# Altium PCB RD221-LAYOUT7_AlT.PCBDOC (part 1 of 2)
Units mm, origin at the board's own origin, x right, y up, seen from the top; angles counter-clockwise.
Board outline 85 x 108 mm, 4 copper layers (TOP, Mid-Layer 1, Mid-Layer 2, BOTTOM), stack 0.711 mm thick; 92 components, 59 nets, 620 pads, 607 vias.
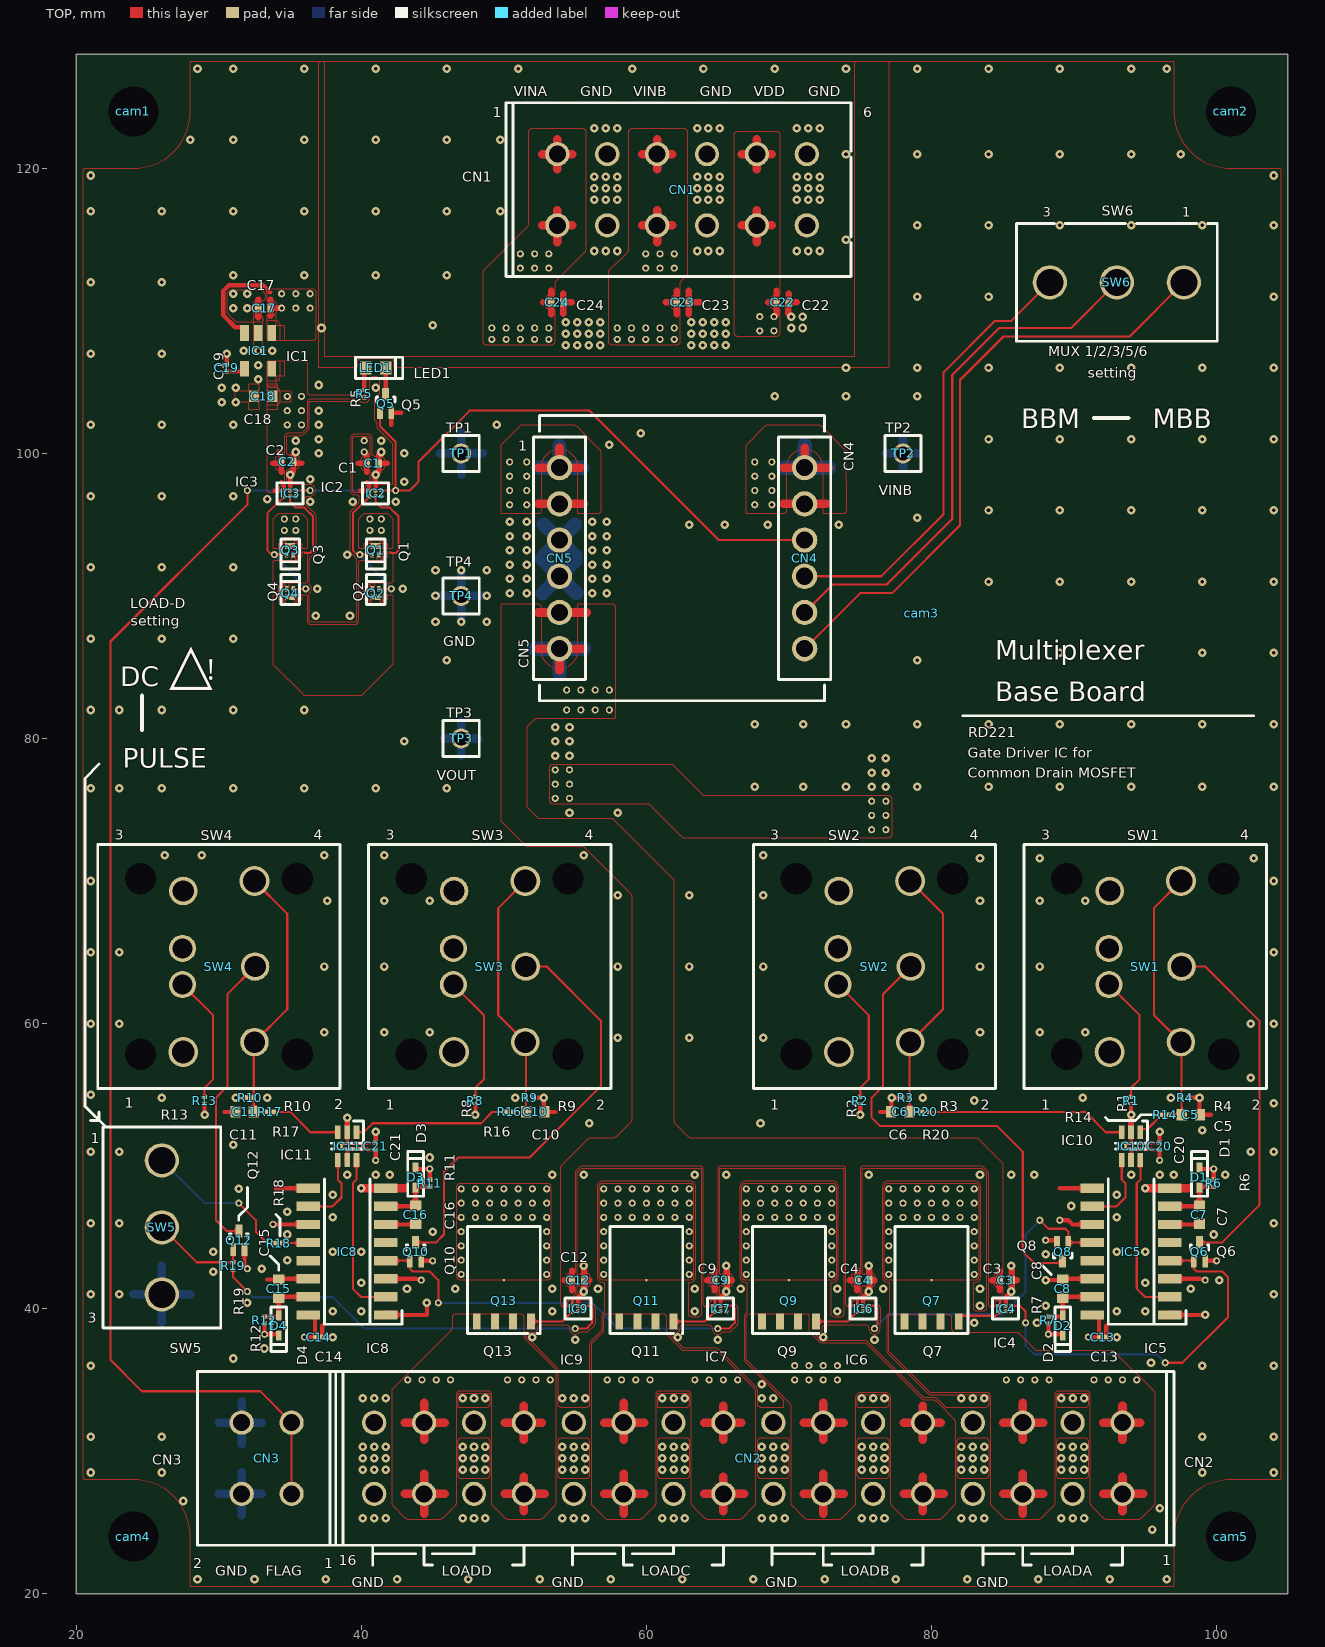
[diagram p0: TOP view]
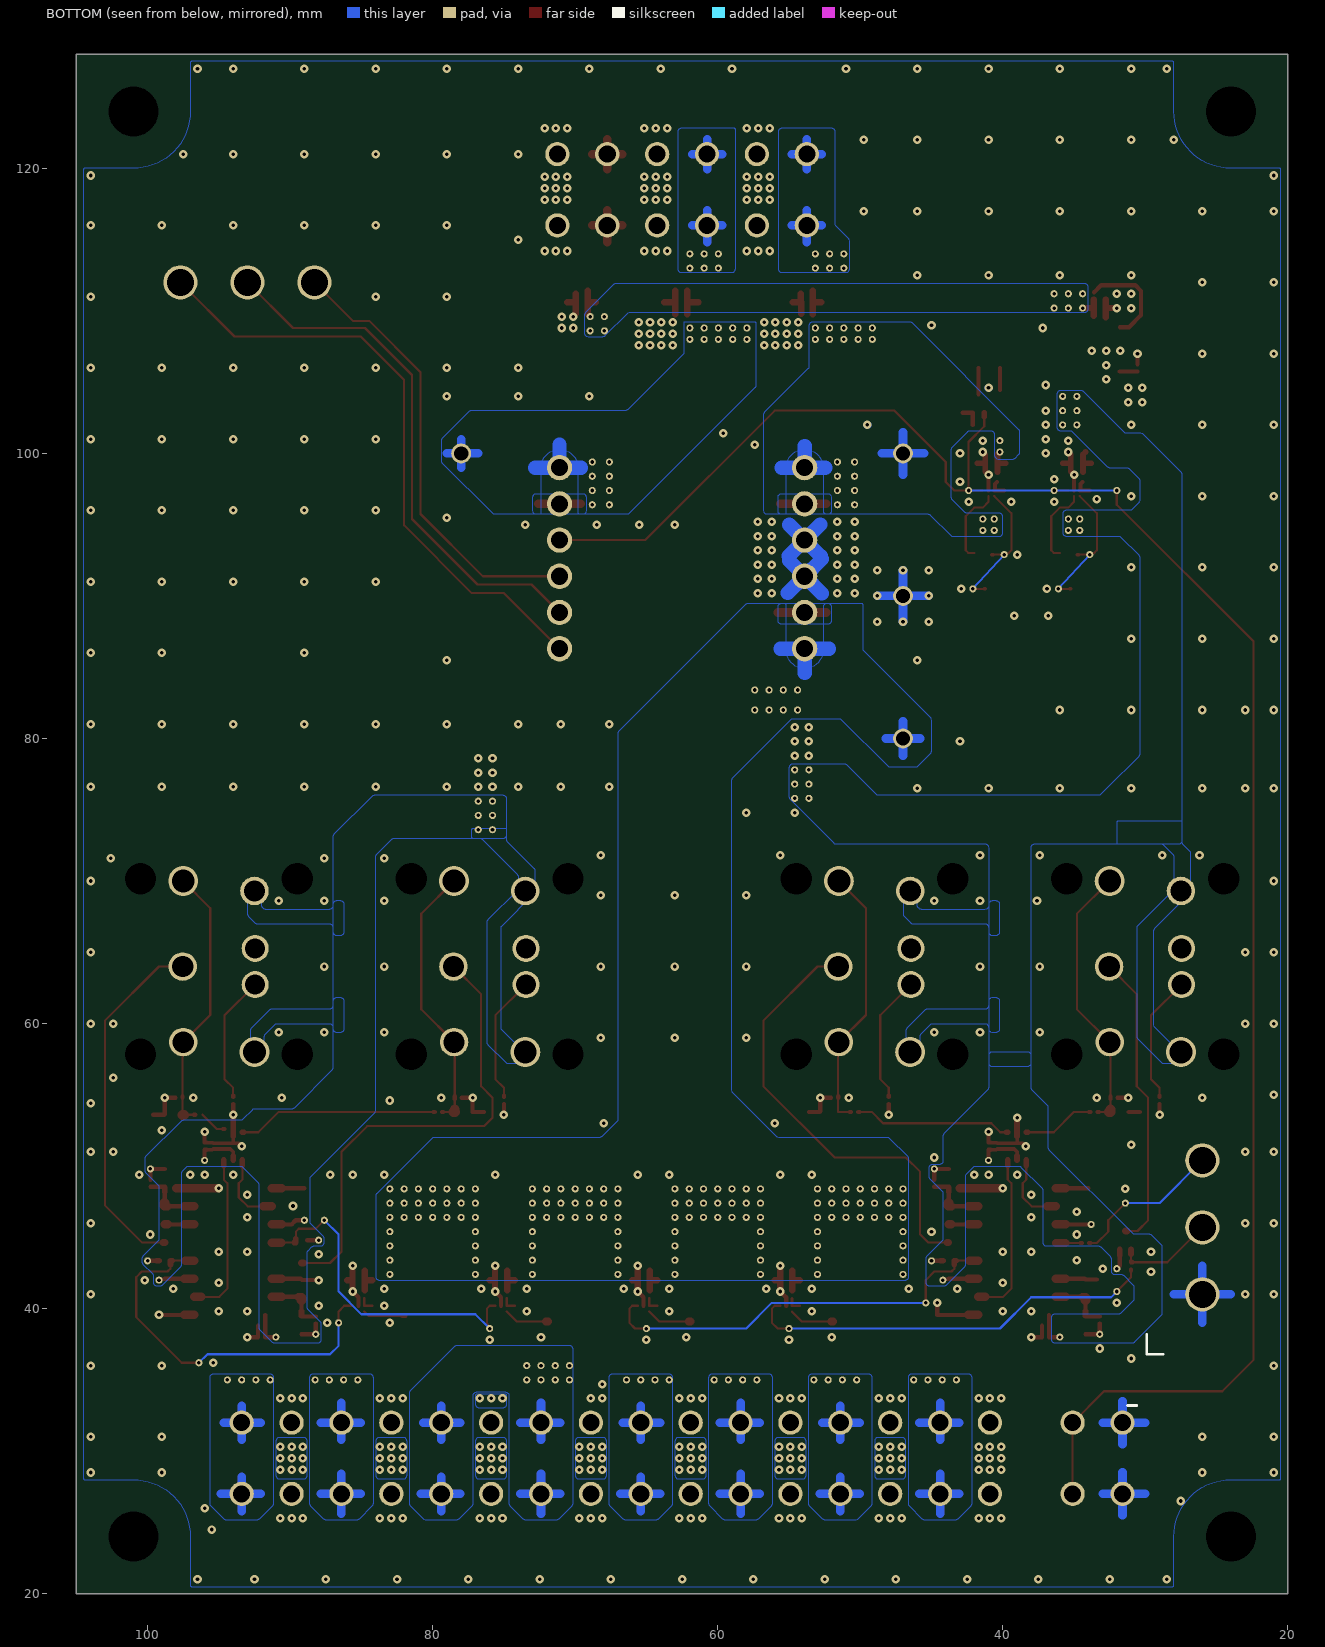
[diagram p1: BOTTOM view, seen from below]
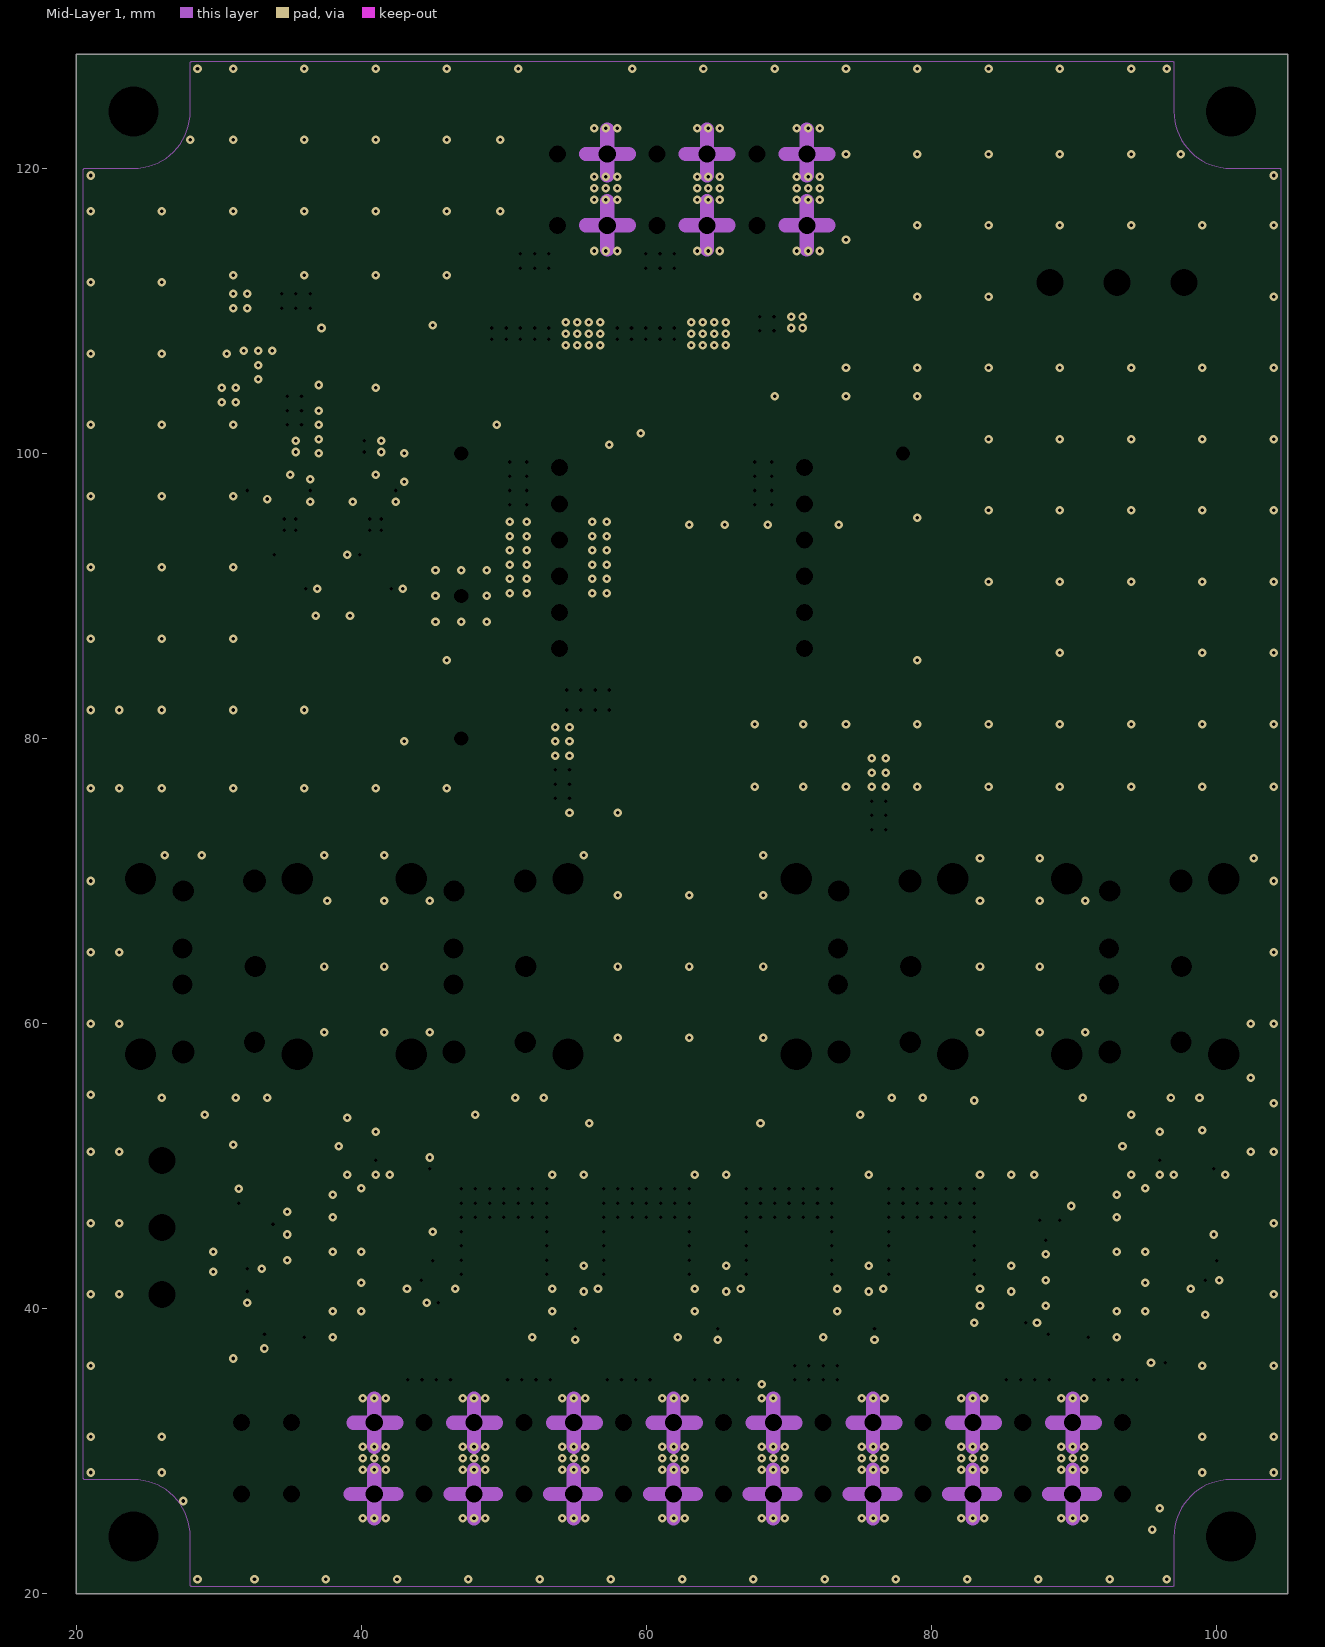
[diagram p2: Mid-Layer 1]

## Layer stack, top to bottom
Top Solder: solder mask 0.0102, Solder Resist, Dk 3.5
TOP: signal copper (thickness not stored)
Mid-Layer 1: signal copper 0.0356
Dielectric2: dielectric 0.32, FR-4, Dk 4.8
Mid-Layer 2: signal copper 0.0356
Dielectric3: dielectric 0.32, FR-4, Dk 4.8
BOTTOM: signal copper (thickness not stored)
Bottom Solder: solder mask 0.0102, Solder Resist, Dk 3.5

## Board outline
20,20 20,128 105,128 105,20

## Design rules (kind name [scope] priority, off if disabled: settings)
AssemblyTestPointUsage [All] p0: scope1count=1 scope1_0_kind=Board scope1_0_value=Board scope2count=1 scope2_0_kind=Board scope2_0_value=Board commentlength=0
AssemblyTestpoint [All] p0: scope1count=1 scope1_0_kind=Board scope1_0_value=Board scope2count=1 scope2_0_kind=Board scope2_0_value=Board commentlength=0
Clearance [All] p0: scope1count=1 scope1_0_kind=Board scope1_0_value=Board scope2count=1 scope2_0_kind=Board scope2_0_value=Board commentlength=0 gap=0.15
Clearance [All] p1: gap=0.15 ignorepadtopadclearanceinfootprint=TRUE except(0.5: Arc-Hole Track-Hole SMDPad-Hole THPad-Hole Via-Hole Fill-Hole Poly-Hole Region-Hole Text-Hole)
ComponentClearance [All] p0: scope1count=1 scope1_0_kind=Board scope1_0_value=Board scope2count=1 scope2_0_kind=Board scope2_0_value=Board commentlength=0 gap=0.254 collisioncheckmode=3
DiffPairsRouting [All] p0: scope1count=1 scope1_0_kind=Board scope1_0_value=Board scope2count=1 scope2_0_kind=Board scope2_0_value=Board commentlength=0
FabricationTestPointUsage [All] p0: scope1count=1 scope1_0_kind=Board scope1_0_value=Board scope2count=1 scope2_0_kind=Board scope2_0_value=Board commentlength=0 valid=0 allowmultiple=FALSE
FabricationTestpoint [All] p0: scope1count=1 scope1_0_kind=Board scope1_0_value=Board scope2count=1 scope2_0_kind=Board scope2_0_value=Board commentlength=0 side=3 testpointundercomponent=TRUE minsize=1.016 maxsize=2.54 preferedsize=1.524 minholesize=0 maxholesize=1.016 preferedholesize=0.813 testpointgrid=0.025
FanoutControl Fanout_BGA [All] p0 off: scope1count=1 scope1_0_kind=Board scope1_0_value=Board scope2count=1 scope2_0_kind=Board scope2_0_value=Board commentlength=69 // Protel DXP Scope 1 Expression Was: IsBGA   Fanout_BGA (Default Rule)
FanoutControl Fanout_LCC [All] p0 off: scope1count=1 scope1_0_kind=Board scope1_0_value=Board scope2count=1 scope2_0_kind=Board scope2_0_value=Board commentlength=69 // Protel DXP Scope 1 Expression Was: IsLCC   Fanout_LCC (Default Rule)
FanoutControl Fanout_SOIC [All] p0 off: scope1count=1 scope1_0_kind=Board scope1_0_value=Board scope2count=1 scope2_0_kind=Board scope2_0_value=Board commentlength=71 // Protel DXP Scope 1 Expression Was: IsSOIC   Fanout_SOIC (Default Rule)
FanoutControl Fanout_Small [All] p0 off: scope1count=1 scope1_0_kind=Board scope1_0_value=Board scope2count=1 scope2_0_kind=Board scope2_0_value=Board commentlength=84 // Protel DXP Scope 1 Expression Was: (CompPinCount < 5)   Fanout_Small (Default Rule)
FanoutControl Fanout_Default [All] p0: scope1count=1 scope1_0_kind=Board scope1_0_value=Board scope2count=1 scope2_0_kind=Board scope2_0_value=Board commentlength=30 // Fanout_Default (Default Rule)
Height [All] p0: scope1count=1 scope1_0_kind=Board scope1_0_value=Board scope2count=1 scope2_0_kind=Board scope2_0_value=Board commentlength=0
HoleSize [All] p0: scope1count=1 scope1_0_kind=Board scope1_0_value=Board scope2count=1 scope2_0_kind=Board scope2_0_value=Board commentlength=0 absolutevalues=TRUE maxlimit=100 minlimit=0.001 maxpercent=80.000 minpercent=20.000
HoleSize [All] p1: absolutevalues=TRUE maxlimit=100 minlimit=0.001 maxpercent=80.000 minpercent=20.000
HoleToHoleClearance [All] p0: scope1count=1 scope1_0_kind=Board scope1_0_value=Board scope2count=1 scope2_0_kind=Board scope2_0_value=Board commentlength=0
HoleToHoleClearance [All] p1: gap=0.4 allowstackedmicrovias=FALSE
LayerPairs [All] p0: scope1count=1 scope1_0_kind=Board scope1_0_value=Board scope2count=1 scope2_0_kind=Board scope2_0_value=Board commentlength=0 enforce=TRUE
MinimumSolderMaskSliver [All] p0: scope1count=1 scope1_0_kind=Board scope1_0_value=Board scope2count=1 scope2_0_kind=Board scope2_0_value=Board commentlength=0
MinimumSolderMaskSliver [All] p1: minsoldermaskwidth=0.1
NetAntennae [All] p0: scope1count=1 scope1_0_kind=Board scope1_0_value=Board scope2count=1 scope2_0_kind=Board scope2_0_value=Board commentlength=0
NetAntennae [All] p1: netantennaetolerance=100
PasteMaskExpansion [All] p0: scope1count=1 scope1_0_kind=Board scope1_0_value=Board scope2count=1 scope2_0_kind=Board scope2_0_value=Board commentlength=0 expansion=0
PlaneClearance [All] p0: scope1count=1 scope1_0_kind=Board scope1_0_value=Board scope2count=1 scope2_0_kind=Board scope2_0_value=Board commentlength=0 clearance=0.001
PlaneClearance [All] p1: clearance=0.001
PlaneConnect [All] p0: scope1count=1 scope1_0_kind=Board scope1_0_value=Board scope2count=1 scope2_0_kind=Board scope2_0_value=Board commentlength=0 planeconnectstyle=Direct reliefexpansion=0.508 reliefentries=4 reliefconductorwidth=0.254 reliefairgap=0.254
PlaneConnect [All] p1: planeconnectstyle=Direct reliefexpansion=0.508 reliefentries=4 reliefconductorwidth=0.254 reliefairgap=0.254
PolygonConnect [All] p0: scope1count=1 scope1_0_kind=Board scope1_0_value=Board scope2count=1 scope2_0_kind=Board scope2_0_value=Board commentlength=0 connectstyle=Direct reliefconductorwidth=0.254 reliefentries=4 polygonreliefangle="90 Angle"
PolygonConnect [All] p1: connectstyle=Direct reliefconductorwidth=0.254 reliefentries=4 polygonreliefangle="90 Angle" airgapwidth=0.254
RoutingCorners [All] p0: scope1count=1 scope1_0_kind=Board scope1_0_value=Board scope2count=1 scope2_0_kind=Board scope2_0_value=Board commentlength=0 cornerstyle=45-Degree minsetback=2.54 maxsetback=2.54
RoutingLayers [All] p0: scope1count=1 scope1_0_kind=Board scope1_0_value=Board scope2count=1 scope2_0_kind=Board scope2_0_value=Board commentlength=0 top layer=Automatic mid layer 1=Automatic mid layer 2=Automatic bottom layer=Automatic
RoutingPriority [All] p0: scope1count=1 scope1_0_kind=Board scope1_0_value=Board scope2count=1 scope2_0_kind=Board scope2_0_value=Board commentlength=0
RoutingTopology [All] p0: scope1count=1 scope1_0_kind=Board scope1_0_value=Board scope2count=1 scope2_0_kind=Board scope2_0_value=Board commentlength=0 topology=Shortest
RoutingVias [All] p0: scope1count=1 scope1_0_kind=Board scope1_0_value=Board scope2count=1 scope2_0_kind=Board scope2_0_value=Board commentlength=0 holewidth=0.1 width=0.1 viastyle="Through Hole" minholewidth=0.001 minwidth=0.001 maxholewidth=100 maxwidth=100
RoutingVias [All] p1: holewidth=0.1 width=0.1 viastyle="Through Hole" minholewidth=0.001 minwidth=0.001 maxholewidth=100 maxwidth=100
ShortCircuit [All] p0: scope1count=1 scope1_0_kind=Board scope1_0_value=Board scope2count=1 scope2_0_kind=Board scope2_0_value=Board commentlength=0 allowed=FALSE
SilkToBoardRegionClearance [All] p0: scope1count=1 scope1_0_kind=Board scope1_0_value=Board scope2count=1 scope2_0_kind=Board scope2_0_value=Board commentlength=0
SilkToSilkClearance [All] p0: scope1count=1 scope1_0_kind=Board scope1_0_value=Board scope2count=1 scope2_0_kind=Board scope2_0_value=Board commentlength=0
SilkToSilkClearance [All] p1: silktosilkclearance=0.001
SilkToSolderMaskClearance [All] p0 off: scope1count=1 scope1_0_kind=Board scope1_0_value=Board scope2count=1 scope2_0_kind=Board scope2_0_value=Board commentlength=44 // Protel DXP Scope 1 Expression Was: IsPad
SilkToSolderMaskClearance [IsPad] p1: minsilkscreentomaskgap=0 clearancetoexposedcopper=TRUE
SolderMaskExpansion [All] p0: scope1count=1 scope1_0_kind=Board scope1_0_value=Board scope2count=1 scope2_0_kind=Board scope2_0_value=Board commentlength=0 expansion=0.001
SolderMaskExpansion [All] p1: expansion=0.001
UnRoutedNet [All] p0: scope1count=1 scope1_0_kind=Board scope1_0_value=Board scope2count=1 scope2_0_kind=Board scope2_0_value=Board commentlength=0
UnpouredPolygon [All] p0: scope1count=1 scope1_0_kind=Board scope1_0_value=Board scope2count=1 scope2_0_kind=Board scope2_0_value=Board commentlength=0
Width [All] p0: scope1count=1 scope1_0_kind=Board scope1_0_value=Board scope2count=1 scope2_0_kind=Board scope2_0_value=Board commentlength=0 maxlimit=1000 minlimit=2539.975 preferedwidth=0
Width [All] p1: maxlimit=1000 minlimit=2539.975 preferedwidth=0 toplayer_minwidth=0 midlayer1_minwidth=0 midlayer2_minwidth=0 bottomlayer_minwidth=0 minimp=50.000000 maximp=50.000000 favimp=50.000000
22 further rules are at their usual default settings.

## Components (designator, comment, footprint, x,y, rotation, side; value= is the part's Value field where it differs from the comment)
C1 "KC00051KD" KC00051KD 40.8,99.3 r0 top
C2 "KC00051KD" KC00051KD 34.8,99.4 r0 top
C3 "KC00051KD" KC00051KD 85.2,42 r0 top
C4 "KC00051KD" KC00051KD 75.2,42 r0 top
C5 "KC00081KD" KC00081KD 98.2,53.6 r0 top
C6 "KC00081KD" KC00081KD 77.8,53.8 r180 top
C7 "KC00081KD" KC00081KD 98.8,46.6 r90 top
C8 "KC00081KD" KC00081KD 89.2,41.4 r270 top
C9 "KC00051KD" KC00051KD 65.2,42 r0 top
C10 "KC00081KD" KC00081KD 52.2,53.8 r0 top
C11 "KC00081KD" KC00081KD 31.8,53.8 r180 top
C12 "KC00051KD" KC00051KD 55.2,42 r0 top
C13 "KC00540KD" KC00540KD 92,38 r180 top
C14 "KC00540KD" KC00540KD 37,38 r180 top
C15 "KC00081KD" KC00081KD 34.2,41.4 r270 top
C16 "KC00081KD" KC00081KD 43.8,46.6 r270 top
C17 "KC00051KD" KC00051KD 33.2,110.2 r180 top
C18 "KC00081KD" KC00081KD 33.1,104 r180 top
C19 "KC00540KD" KC00540KD 30.55,106 r270 top
C20 "KC00540KD" KC00540KD 96,51.4 r270 top
C21 "KC00540KD" KC00540KD 41,51.4 r270 top
C22 "KC00051KD" KC00051KD 69.55,110.6 r0 top
C23 "KC00051KD" KC00051KD 62.55,110.6 r0 top
C24 "KC00051KD" KC00051KD 53.75,110.6 r0 top
cam1 "NTC350" NTC350 24,124 r180 top
cam2 "NTC350" NTC350 101,124 r180 top
cam3 "UTOS26N" UTOS26N 79.3,88.788 r0 top
cam4 "NTC350" NTC350 24,24 r180 top
cam5 "NTC350" NTC350 101,24 r180 top
CN1 "CU12010TD" CU12010TD 53.75,116 r0 top
CN2 "CU12030TD" CU12030TD 93.4,32 r180 top
CN3 "CU12020TD" CU12020TD 35.1,32 r180 top
CN4 "CU11170TD" CU11170TD 71.1,86.3 r90 top
CN5 "CU11170TD" CU11170TD 53.9,99 r270 top
D1 "D8101D1KD" D8101D1KD 98.8,49.2 r90 top
D2 "D8101D1KD" D8101D1KD 89.2,38.8 r270 top
D3 "D8101D1KD" D8101D1KD 43.8,49.2 r90 top
D4 "D8101D1KD" D8101D1KD 34.2,38.8 r270 top
IC1 "MM00631KD" MM00631KD 32.75,107.2 r180 top
IC2 "BA10620KD" BA10620KD 41,97.2 r0 top
IC3 "BA10620KD" BA10620KD 35,97.2 r0 top
IC4 "BA10620KD" BA10620KD 85.2,40 r0 top
IC5 "SP10580KD" SP10580KD 94,44 r90 top
IC6 "BA10620KD" BA10620KD 75.2,40 r0 top
IC7 "BA10620KD" BA10620KD 65.2,40 r0 top
IC8 "SP10580KD" SP10580KD 39,44 r90 top
IC9 "BA10620KD" BA10620KD 55.2,40 r0 top
IC10 "MM00451KD" MM00451KD 94,51.4 r180 top
IC11 "MM00451KD" MM00451KD 39,51.4 r180 top
LED1 "KC01110KD" KC01110KD 41,106 r0 top
Q1 "LA10710KD" LA10710KD 41,93.2 r90 top
Q2 "LA10710KD" LA10710KD 41,90.2 r270 top
Q3 "LA10710KD" LA10710KD 35,93.2 r90 top
Q4 "LA10710KD" LA10710KD 35,90.2 r270 top
Q5 "MM11010KD" MM11010KD 41.7,103.5 r0 top
Q6 "MM11010KD" MM11010KD 98.8,44 r0 top
Q7 "SN10261KD" SN10261KD 80,42 r0 top
Q8 "MM11010KD" MM11010KD 89.2,44 r180 top
Q9 "SN10261KD" SN10261KD 70,42 r0 top
Q10 "MM11010KD" MM11010KD 43.8,44 r0 top
Q11 "SN10261KD" SN10261KD 60,42 r0 top
Q12 "MM11010KD" MM11010KD 31.4,44.8 r0 top
Q13 "SN10261KD" SN10261KD 50,42 r0 top
R1 "KC00540KD" KC00540KD 94,54.6 r270 top
R2 "KC00540KD" KC00540KD 75,54.6 r270 top
R3 "KC00540KD" KC00540KD 78.2,54.8 r180 top
R4 "KC00540KD" KC00540KD 97.8,54.8 r0 top
R5 "KC00540KD" KC00540KD 40.2,104.2 r270 top
R6 "KC00540KD" KC00540KD 99.8,48.8 r270 top
R7 "KC00540KD" KC00540KD 88.2,39.2 r90 top
R8 "KC00540KD" KC00540KD 48,54.6 r270 top
R9 "KC00540KD" KC00540KD 51.8,54.8 r0 top
R10 "KC00540KD" KC00540KD 32.2,54.8 r180 top
R11 "KC00540KD" KC00540KD 44.8,48.8 r270 top
R12 "KC00540KD" KC00540KD 33.2,39.2 r90 top
R13 "KC00540KD" KC00540KD 29,54.6 r270 top
R14 "KC00540KD" KC00540KD 96.4,53.6 r0 top
R16 "KC00540KD" KC00540KD 50.4,53.8 r0 top
R17 "KC00540KD" KC00540KD 33.6,53.8 r0 top
R18 "KC00540KD" KC00540KD 34.2,44.6 r0 top
R19 "KC00540KD" KC00540KD 31,43 r270 top
R20 "KC00540KD" KC00540KD 79.6,53.8 r0 top
SW1 "OD11430TD" OD11430TD 95,64 r0 top
SW2 "OD11430TD" OD11430TD 76,64 r0 top
SW3 "OD11430TD" OD11430TD 49,64 r0 top
SW4 "OD11430TD" OD11430TD 30,64 r0 top
SW5 "OD11420TD" OD11420TD 26,50.4 r270 top
SW6 "OD11420TD" OD11420TD 97.7,112 r180 top
TP1 "DP002X0KD" DP002X0KD 47,100 r0 top
TP2 "DP002X0KD" DP002X0KD 78,100 r0 top
TP3 "DP002X0KD" DP002X0KD 47,80 r0 top
TP4 "DP002X0KD" DP002X0KD 47,90 r0 top

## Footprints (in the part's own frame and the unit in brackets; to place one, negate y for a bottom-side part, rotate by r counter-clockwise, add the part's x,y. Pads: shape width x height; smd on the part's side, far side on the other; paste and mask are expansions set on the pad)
BA10620KD [mm] "KC00080BKP"
  round 0.325 smd paste-0.325 mask+0: A1(-0.4,-0.2) A2(-0.4,0.2) B1(0,-0.2) B2(0,0.2) C1(0.4,-0.2) C2(0.4,0.2)
  silkscreen extent -0.91,-0.74 0.91,0.74
CU11170TD [mil] "KC00080BKP"
  round 70 / inner round 0 / far side round 70 hole 47.24 paste-70 mask+0: 1(0,0) 2(100,0) 3(200,0) 4(300,0) 5(400,0) 6(500,0)
  silkscreen extent -85,-72 585,72
CU12010TD [mm] "KC00080BKP"
  round 1.7 / inner round 0 / far side round 1.7 hole 1.2 paste-1.8 mask+0: 1(0,0) 1A(0,5) 2(3.5,0) 2A(3.5,5) 3(7,0) 3A(7,5) 4(10.5,0) 4A(10.5,5) 5(14,0) 5A(14,5) 6(17.5,0) 6A(17.5,5)
  silkscreen extent -3.6,-3.6 20.6,8.6
CU12020TD [mm] "KC00080BKP"
  round 1.7 / inner round 0 / far side round 1.7 hole 1.2 paste-1.8 mask+0: 1(0,0) 1A(0,5) 2(3.5,0) 2A(3.5,5)
  silkscreen extent -3.6,-3.6 6.6,8.6
CU12030TD [mm] "KC00080BKP"
  round 1.7 / inner round 0 / far side round 1.7 hole 1.2 paste-1.8 mask+0: 1(0,0) 1A(0,5) 2(3.5,0) 2A(3.5,5) 3(7,0) 3A(7,5) 4(10.5,0) 4A(10.5,5) 5(14,0) 5A(14,5) 6(17.5,0) 6A(17.5,5) 7(21,0) 7A(21,5) 8(24.5,0) 8A(24.5,5) 9(28,0) 9A(28,5) 10(31.5,0) 10A(31.5,5) 11(35,0) 11A(35,5) 12(38.5,0) 12A(38.5,5) 13(42,0) 13A(42,5) 14(45.5,0) 14A(45.5,5) 15(49,0) 15A(49,5) 16(52.5,0) 16A(52.5,5)
  silkscreen extent -3.6,-3.6 55.6,8.6
D8101D1KD [mm] "KC00080BKP"
  rect 0.7x0.4 smd paste-0.7 mask+0: A(-0.7,0) C(0.7,0)
  silkscreen extent -1.32,-0.55 1.82,0.55
DP002X0KD [mil] "KC00080BKP"
  round 55 / inner round 0 / far side round 55 hole 39.37 paste-55 mask+0: 1(0,0)
  silkscreen extent -50,-50 50,50
KC00051KD [mm] "KC00080BKP"
  rect 0.45x0.55 smd paste-0.55 mask+0: 1(-0.425,0) 2(0.425,0)
KC00081KD [mm] "KC00080BKP"
  rect 0.72x0.8 smd paste-0.8 mask+0: 1(-0.64,0) 2(0.64,0)
KC00540KD [mm] "KC00080BKP"
  rect 0.3x0.35 smd paste-0.35 mask+0: 1(-0.25,0) 2(0.25,0)
KC01110KD [mm] "KC00080BKP"
  rect 0.8x0.9 smd paste-0.9 mask+0: A(-0.7,0) C(0.7,0)
  silkscreen extent -1.4,-0.75 1.9,0.75
LA10710KD [mm] "KC00080BKP"
  rect 0.4x0.7 smd paste-0.7 mask+0: D(0.3,0)
  rect 0.4x0.25 smd paste-0.4 mask+0: G(-0.3,0.225) S(-0.3,-0.225)
  silkscreen extent -1.3,-0.65 0.8,0.65
MM00451KD [mm] "KC00080BKP"
  rect 0.4x0.95 smd paste-0.95 mask+0: 1(-0.65,-0.975) 2(0,-0.975) 3(0.65,-0.975) 4(0.65,0.975) 5(0,0.975) 6(-0.65,0.975)
  silkscreen extent -1.15,-1.75 1.1,0.2
MM00631KD [mm] "KC00080BKP"
  rect 0.6x1.1 smd paste-1.1 mask+0: 1(-0.95,-1.25) 2(0,-1.25) 3(0.95,-1.25) 4(0.95,1.25) 5(-0.95,1.25)
MM11010KD [mm] "KC00080BKP"
  rect 0.4x0.9 smd paste-0.9 mask+0: B(-0.4,-0.65) E(0.4,-0.65)
  rect 0.5x0.9 smd paste-0.9 mask+0: C(0,0.65)
  silkscreen extent -0.65,0.1 0.65,0.45
NTC350 [mm] "KC00080BKP"
  round 0 hole 3.5 unplated paste-4.064 mask+0: ""(0,0)
OD11420TD [mm] "KC00080BKP"
  round 2.4 / inner round 0 / far side round 2.4 hole 1.9 paste-2.5 mask+0: 1(0,0) 2(4.7,0) 3(9.4,0)
  silkscreen extent -2.35,-4.13 11.75,4.13
OD11430TD [mm] "KC00080BKP"
  round 2.1 / inner round 0 / far side round 2.1 hole 1.6 paste-2.2 mask+0: 1(-2.5,-6) 4(2.5,6)
  round 2 / inner round 0 / far side round 2 hole 1.5 paste-2.1 mask+0: 2(2.5,-5.3) 3(-2.5,5.3) LC(2.54,0)
  round 1.9 / inner round 0 / far side round 1.9 hole 1.4 paste-2 mask+0: L1(-2.55,1.27) L2(-2.55,-1.27)
  round 0 hole 2.2 unplated paste-2.54 mask+0: ""(-5.5,-6.15) ""(-5.5,6.15) ""(5.5,-6.15) ""(5.5,6.15)
  silkscreen extent -8.5,-8.55 8.5,8.55
SN10261KD [mm] "KC00080BKP"
  rect 0.55x1.1 smd paste-1.1 mask+0: 1(-1.905,-2.9) 2(-0.635,-2.9) 3(0.635,-2.9) 4(1.905,-2.9)
  round 0.178 smd paste-0.178 mask+0: 5(0,0)
  silkscreen extent -2.55,-3.75 2.55,3.75
SP10580KD [mm] "KC00080BKP"
  rect 0.65x1.65 smd paste-1.65 mask+0: 1(-4.445,-2.725) 2(-3.175,-2.725) 3(-1.905,-2.725) 4(-0.635,-2.725) 5(0.635,-2.725) 6(1.905,-2.725) 7(3.175,-2.725) 8(4.445,-2.725) 9(4.445,2.725) 10(3.175,2.725) 11(1.905,2.725) 12(0.635,2.725) 13(-0.635,2.725) 14(-1.905,2.725) 15(-3.175,2.725) 16(-4.445,2.725)
  silkscreen extent -5.1,-3.85 5.1,1.6
UTOS26N [mm] "KC00080BKP"

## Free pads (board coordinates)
  round 0.5 / inner round 0 / far side round 0.5 hole 0.25 paste-0.5 mask+0: ""(31.4,47.4) ""(32,41.2) ""(32,42.8) ""(32,97.4) ""(33.2,38.2) ""(33.8,45.905) ""(33.9,92.9) ""(34.4,110.2) ""(34.4,111.2) ""(34.6,94.6) ""(34.6,95.4) ""(34.8,102) ""(34.8,103) ""(34.8,104) ""(35.4,94.6) ""(35.4,95.4) ""(35.4,110.2) ""(35.4,111.2) ""(35.8,102) ""(35.8,103) ""(35.8,104) ""(36,38) ""(36.1,90.5) ""(36.4,97.4) ""(36.4,110.2) ""(36.4,111.2) ""(39.9,92.9) ""(40.2,100.1) ""(40.2,100.9) ""(40.6,94.6) ""(40.6,95.4) ""(41,50.4) ""(41.4,94.6) ""(41.4,95.4) ""(42.1,90.5) ""(42.4,97.4) ""(43.25,35) ""(44.2,42) ""(44.25,35) ""(44.8,49.8) ""(45,43.35) ""(45.25,35) ""(45.4,40.4) ""(46.25,35) ""(47,42.4) ""(47,43.4) ""(47,44.4) ""(47,45.4) ""(47,46.4) ""(47,47.4) ""(47,48.4) ""(48,46.4) ""(48,47.4) ""(48,48.4) ""(49,46.4) ""(49,47.4) ""(49,48.4) ""(49.15,108) ""(49.15,108.8) ""(50,46.4) ""(50,47.4) ""(50,48.4) ""(50.15,108) ""(50.15,108.8) ""(50.25,35) ""(50.4,96.4) ""(50.4,97.4) ""(50.4,98.4) ""(50.4,99.4) ""(51,46.4) ""(51,47.4) ""(51,48.4) ""(51.15,108) ""(51.15,108.8) ""(51.15,113) ""(51.15,114) ""(51.25,35) ""(51.6,96.4) ""(51.6,97.4) ""(51.6,98.4) ""(51.6,99.4) ""(52,46.4) ""(52,47.4) ""(52,48.4) ""(52.15,108) ""(52.15,108.8) ""(52.15,113) ""(52.15,114) ""(52.25,35) ""(53,42.4) ""(53,43.4) ""(53,44.4) ""(53,45.4) ""(53,46.4) ""(53,47.4) ""(53,48.4) ""(53.15,108) ""(53.15,108.8) ""(53.15,113) ""(53.15,114) ""(53.25,35) ""(53.6,75.8) ""(53.6,76.8) ""(53.6,77.8) ""(54.4,82) ""(54.4,83.4) ""(54.6,75.8) ""(54.6,76.8) ""(54.6,77.8) ""(55,38.6) ""(55.4,82) ""(55.4,83.4) ""(56.4,82) ""(56.4,83.4) ""(57,42.4) ""(57,43.4) ""(57,44.4) ""(57,45.4) ""(57,46.4) ""(57,47.4) ""(57,48.4) ""(57.25,35) ""(57.4,82) ""(57.4,83.4) ""(57.95,108) ""(57.95,108.8) ""(58,46.4) ""(58,47.4) ""(58,48.4) ""(58.25,35) ""(58.95,108) ""(58.95,108.8) ""(59,46.4) ""(59,47.4) ""(59,48.4) ""(59.25,35) ""(59.95,108) ""(59.95,108.8) ""(59.95,113) ""(59.95,114) ""(60,46.4) ""(60,47.4) ""(60,48.4) ""(60.25,35) ""(60.95,108) ""(60.95,108.8) ""(60.95,113) ""(60.95,114) ""(61,46.4) ""(61,47.4) ""(61,48.4) ""(61.95,108) ""(61.95,108.8) ""(61.95,113) ""(61.95,114) ""(62,46.4) ""(62,47.4) ""(62,48.4) ""(63,42.4) ""(63,43.4) ""(63,44.4) ""(63,45.4) ""(63,46.4) ""(63,47.4) ""(63,48.4) ""(63.4,35) ""(64.4,35) ""(65,38.6) ""(65.4,35) ""(66.4,35) ""(67,42.4) ""(67,43.4) ""(67,44.4) ""(67,45.4) ""(67,46.4) ""(67,47.4) ""(67,48.4) ""(67.6,96.4) ""(67.6,97.4) ""(67.6,98.4) ""(67.6,99.4) ""(67.95,108.6) ""(67.95,109.6) ""(68,46.4) ""(68,47.4) ""(68,48.4) ""(68.8,96.4) ""(68.8,97.4) ""(68.8,98.4) ""(68.8,99.4) ""(68.95,108.6) ""(68.95,109.6) ""(69,46.4) ""(69,47.4) ""(69,48.4) ""(70,46.4) ""(70,47.4) ""(70,48.4) ""(70.4,35) ""(70.4,36) ""(71,46.4) ""(71,47.4) ""(71,48.4) ""(71.4,35) ""(71.4,36) ""(72,46.4) ""(72,47.4) ""(72,48.4) ""(72.4,35) ""(72.4,36) ""(73,42.4) ""(73,43.4) ""(73,44.4) ""(73,45.4) ""(73,46.4) ""(73,47.4) ""(73,48.4) ""(73.4,35) ""(73.4,36) ""(75.8,73.6) ""(75.8,74.6) ""(75.8,75.6) ""(76,38.6) ""(76.8,73.6) ""(76.8,74.6) ""(76.8,75.6) ""(77,42.4) ""(77,43.4) ""(77,44.4) ""(77,45.4) ""(77,46.4) ""(77,47.4) ""(77,48.4) ""(78,46.4) ""(78,47.4) ""(78,48.4) ""(79,46.4) ""(79,47.4) ""(79,48.4) ""(80,46.4) ""(80,47.4) ""(80,48.4) ""(81,46.4) ""(81,47.4) ""(81,48.4) ""(82,46.4) ""(82,47.4) ""(82,48.4) ""(83,42.4) ""(83,43.4) ""(83,44.4) ""(83,45.4) ""(83,46.4) ""(83,47.4) ""(83,48.4) ""(85.25,35) ""(86.25,35) ""(86.6,39) ""(87.25,35) ""(87.6,46.2) ""(88,44.8) ""(88.2,38.2) ""(88.25,35) ""(89,46.2) ""(91,38) ""(91.4,35) ""(92.4,35) ""(93.4,35) ""(94.4,35) ""(96,50.4) ""(96.4,36.2) ""(99.2,42) ""(99.8,49.8) ""(100,43.35)

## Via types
v1: diameter 0.6, hole 0.25, TOP to BOTTOM, 607 vias

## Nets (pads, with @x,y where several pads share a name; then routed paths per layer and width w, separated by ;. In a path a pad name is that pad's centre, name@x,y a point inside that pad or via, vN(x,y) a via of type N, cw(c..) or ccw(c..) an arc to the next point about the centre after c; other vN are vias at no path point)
FLAG: CN3.1 CN3.1A CN4.4 IC2.C2 IC3.C2 pad.@32,97.4 pad.@36.4,97.4 pad.@42.4,97.4 Q5.B | length 138.4
  TOP w0.15: pad.@32,97.4 32,96.4 22.4,86.8 22.4,36.4 24.6,34.2 32.9,34.2 CN3.1@35.1,32 CN3.1A@35.1,27 ; IC3.C2@35.4,97.4 pad.@36.4,97.4 ; Q5.B@41.3,102.58 41.3,101.9 42.4,100.8 pad.@42.4,97.4 ; IC2.C2@41.4,97.4 pad.@42.4,97.4 ; CN4.4@71.1,93.92 65.08,93.92 56,103 47.6,103 44,99.4 44,98 43.4,97.4 pad.@42.4,97.4
  TOP w0.4: Q5.B@41.3,102.58 Q5.B@41.3,102.85
  BOTTOM w0.15: pad.@32,97.4 pad.@36.4,97.4 pad.@42.4,97.4
GND: C1.2 C2.2 C3.2 C4.2 C5.2 C6.2 C8.1 C9.2 C10.2 C11.2 C12.2 C13.1 C14.1 C15.1 C17.2 C18.2 C19.1 C20.1 C21.1 C22.2 C23.2 C24.2 CN1.2 CN1.2A CN1.4 CN1.4A CN1.6 CN1.6A CN2.2 CN2.2A CN2.4 CN2.4A CN2.6 CN2.6A CN2.8 CN2.8A CN2.10 CN2.10A CN2.12 CN2.12A CN2.14 CN2.14A CN2.16 CN2.16A CN3.2 CN3.2A CN5.3 CN5.4 IC1.2 IC2.B2 IC3.B2 IC4.B2 IC5.1 IC5.8 IC5.9 IC5.14 IC6.B2 IC7.B2 IC8.1 IC8.8 IC8.9 IC8.14 IC9.B2 IC10.2 IC11.2 Q5.E R1.2 R2.2 R3.2 R4.2 R8.2 R9.2 R10.2 R13.2 SW5.3 TP4.1 | length 259.1
  TOP w0.25: v1(38.4,51.4) 38.6,51.6 39,51.6 ; IC11.2@39,52.1 39,51.6 ; C21.1@40.868,51.65 40.45,51.65 40.4,51.6 39,51.6 ; v1(93.4,51.4) 93.6,51.6 94,51.6 ; IC10.2@94,52.1 94,51.6 ; C20.1@95.868,51.65 95.45,51.65 95.4,51.6 94,51.6
  TOP w0.3: v1(29,53.6) R13.2@29,54.35 ; 30.4,53.8 C11.2@31.16,53.8 ; C19.1@30.55,106.25 v1(30.55,107) ; v1(31.2,54.8) R10.2@31.95,54.8 ; 33.4,42.04 C15.1@34.2,42.04 ; 34,48.445 IC8.9@35.582,48.445 ; C15.1@34.255,42.095 IC8.14@35.582,42.095 ; IC3.B2@35,97.4 v1(35,98.5) ; 37.25,38.8 C14.1@37.25,38 v1(38,38) ; C21.1@40.868,51.65 C21.1@41,51.65 v1(41,52.4) ; IC2.B2@41,97.4 v1(41,98.5) ; 42.1,102 Q5.E@42.1,102.85 42.8,102.85 ; IC8.1@42.418,39.555 44.6,39.555 v1(44.6,40.4) ; v1(48,53.6) R8.2@48,54.35 ; R9.2@52.05,54.8 v1(52.8,54.8) C10.2@52.8,53.84 ; C10.2@52.84,53.8 53.6,53.8 ; IC9.B2@55.2,40.2 55.2,40.8 v1(55.6,41.2) ; IC7.B2@65.2,40.2 65.2,40.8 v1(65.6,41.2) ; v1(75,53.6) R2.2@75,54.35 ; IC6.B2@75.2,40.2 75.2,40.8 v1(75.6,41.2) ; 76.4,53.8 C6.2@77.16,53.8 ; C6.2@77.2,53.8 v1(77.2,54.8) R3.2@77.95,54.8 ; IC4.B2@85.2,40.2 85.2,40.8 v1(85.6,41.2) ; v1(88,42) C8.1@89.16,42 ; 89,48.445 IC5.9@90.582,48.445 ; C8.1@89.255,42.095 IC5.14@90.582,42.095 ; 92.25,38.8 C13.1@92.25,38 v1(93,38) ; v1(94,53.6) R1.2@94,54.35 ; C20.1@95.868,51.65 C20.1@96,51.65 v1(96,52.4) ; IC5.1@97.418,39.555 v1(99.2,39.555) ; R4.2@98.05,54.8 v1(98.8,54.8) C5.2@98.8,53.64 ; C5.2@98.84,53.6 99.6,53.6
  TOP w0.4: v1(35,98.5) 35.225,98.725 C2.2@35.225,99.3 ; v1(35.4,100.1) 35.225,99.925 C2.2@35.225,99.4 C2.2@35.225,99.3 ; 35.8,99.3 C2.2@35.225,99.3 ; IC11.2@39,52.1 IC11.2@39,52.375 v1(39,53.4) ; v1(41,98.5) 41.225,98.725 C1.2@41.225,99.3 ; v1(41.4,100.1) 41.225,99.925 C1.2@41.225,99.3 ; 41.8,99.3 C1.2@41.225,99.3 ; IC10.2@94,52.1 IC10.2@94,52.375 v1@94,53.4
  TOP w0.45: v1(32,110.2) C17.2@32.775,110.2 ; 32.775,109.55 C17.2@32.775,110.2 ; 32.775,110.8 C17.2@32.775,110.2 ; 54.15,109.8 C24.2@54.15,110.6 ; 54.175,111.2 C24.2@54.175,110.6 54.75,110.6 ; v1@55.625,41.4 C12.2@55.625,42 ; 55.625,42.65 C12.2@55.625,42 ; 56,42 C12.2@55.625,42 ; 62.975,109.775 C23.2@62.975,110.6 ; 62.975,111.4 C23.2@62.975,110.6 ; 63.75,110.6 C23.2@62.975,110.6 ; v1@65.625,41.4 C9.2@65.625,42 ; 65.625,42.65 C9.2@65.625,42 ; 66,42 C9.2@65.625,42 ; v1@69.95,109.8 C22.2@69.95,110.6 ; 69.975,111.2 C22.2@69.975,110.6 70.55,110.6 ; v1@75.625,41.4 C4.2@75.625,42 ; 75.625,42.65 C4.2@75.625,42 ; 76,42 C4.2@75.625,42 ; v1@85.625,41.4 C3.2@85.625,42 ; 85.625,42.65 C3.2@85.625,42 ; 86,42 C3.2@85.625,42
  TOP w0.6: IC8.14@35.582,42.095 IC8.14@36.275,42.095 ; IC8.9@35.582,48.445 IC8.9@36.275,48.445 ; v1(40,48.445) IC8.8@41.725,48.445 43,48.445 ; IC8.1@41.725,39.555 IC8.1@42.418,39.555 ; IC5.14@90.582,42.095 IC5.14@91.275,42.095 ; IC5.9@90.582,48.445 IC5.9@91.275,48.445 ; v1(95,48.445) IC5.8@96.725,48.445 98,48.445 ; IC5.1@96.725,39.555 IC5.1@97.418,39.555
  Mid-Layer 1 w1: 39.25,27 CN2.16A@40.9,27 ; 39.45,32 CN2.16@40.9,32 ; v1(40.9,25.3) CN2.16A@40.9,27 ; v1(40.9,28.7) CN2.16A@40.9,27 ; v1(40.9,30.3) CN2.16@40.9,32 ; v1(40.9,33.7) CN2.16@40.9,32 ; 42.45,27 CN2.16A@40.9,27 ; 42.45,32 CN2.16@40.9,32 ; 46.25,27 CN2.14A@47.9,27 ; 46.45,32 CN2.14@47.9,32 ; v1(47.9,25.3) CN2.14A@47.9,27 ; v1(47.9,28.7) CN2.14A@47.9,27 ; v1(47.9,30.3) CN2.14@47.9,32 ; v1(47.9,33.7) CN2.14@47.9,32 ; 49.45,27 CN2.14A@47.9,27 ; 49.45,32 CN2.14@47.9,32 ; 53.25,27 CN2.12A@54.9,27 ; 53.45,32 CN2.12@54.9,32 ; v1(54.9,25.3) CN2.12A@54.9,27 ; v1(54.9,28.7) CN2.12A@54.9,27 ; v1(54.9,30.3) CN2.12@54.9,32 ; v1(54.9,33.7) CN2.12@54.9,32 ; 55.75,116 CN1.2@57.25,116 ; 55.75,121 CN1.2A@57.25,121 ; 56.45,27 CN2.12A@54.9,27 ; 56.45,32 CN2.12@54.9,32 ; v1@57.25,114.3 CN1.2@57.25,116 ; v1@57.25,117.7 CN1.2@57.25,116 ; v1@57.25,119.5 CN1.2A@57.25,121 ; v1@57.25,122.7 CN1.2A@57.25,121 ; 58.75,116 CN1.2@57.25,116 ; 58.75,121 CN1.2A@57.25,121 ; 60.25,27 CN2.10A@61.9,27 ; 60.45,32 CN2.10@61.9,32 ; v1(61.9,25.3) CN2.10A@61.9,27 ; v1(61.9,28.7) CN2.10A@61.9,27 ; v1(61.9,30.3) CN2.10@61.9,32 ; v1(61.9,33.7) CN2.10@61.9,32 ; 62.75,116 CN1.4@64.25,116 ; 62.75,121 CN1.4A@64.25,121 ; 63.45,27 CN2.10A@61.9,27 ; 63.45,32 CN2.10@61.9,32 ; v1@64.25,114.3 CN1.4@64.25,116 ; v1@64.25,117.7 CN1.4@64.25,116 ; v1@64.25,119.5 CN1.4A@64.25,121 ; v1@64.25,122.7 CN1.4A@64.25,121 ; 65.75,116 CN1.4@64.25,116 ; 65.75,121 CN1.4A@64.25,121 ; 67.25,27 CN2.8A@68.9,27 ; 67.45,32 CN2.8@68.9,32 ; v1(68.9,25.3) CN2.8A@68.9,27 ; v1(68.9,28.7) CN2.8A@68.9,27 ; v1(68.9,30.3) CN2.8@68.9,32 ; v1(68.9,33.7) CN2.8@68.9,32 ; 69.75,116 CN1.6@71.25,116 ; 69.75,121 CN1.6A@71.25,121 ; 70.45,27 CN2.8A@68.9,27 ; 70.45,32 CN2.8@68.9,32 ; v1@71.25,114.3 CN1.6@71.25,116 ; v1@71.25,117.7 CN1.6@71.25,116 ; v1@71.25,119.5 CN1.6A@71.25,121 ; v1@71.25,122.7 CN1.6A@71.25,121 ; 72.75,116 CN1.6@71.25,116 ; 72.75,121 CN1.6A@71.25,121 ; 74.25,27 CN2.6A@75.9,27 ; 74.45,32 CN2.6@75.9,32 ; v1(75.9,25.3) CN2.6A@75.9,27 ; v1(75.9,28.7) CN2.6A@75.9,27 ; v1(75.9,30.3) CN2.6@75.9,32 ; v1(75.9,33.7) CN2.6@75.9,32 ; 77.45,27 CN2.6A@75.9,27 ; 77.45,32 CN2.6@75.9,32 ; 81.25,27 CN2.4A@82.9,27 ; 81.45,32 CN2.4@82.9,32 ; v1(82.9,25.3) CN2.4A@82.9,27 ; v1(82.9,28.7) CN2.4A@82.9,27 ; v1(82.9,30.3) CN2.4@82.9,32 ; v1(82.9,33.7) CN2.4@82.9,32 ; 84.45,27 CN2.4A@82.9,27 ; 84.45,32 CN2.4@82.9,32 ; 88.25,27 CN2.2A@89.9,27 ; 88.45,32 CN2.2@89.9,32 ; v1(89.9,25.3) CN2.2A@89.9,27 ; v1(89.9,28.7) CN2.2A@89.9,27 ; v1(89.9,30.3) CN2.2@89.9,32 ; v1(89.9,33.7) CN2.2@89.9,32 ; 91.45,27 CN2.2A@89.9,27 ; 91.45,32 CN2.2@89.9,32
  BOTTOM w0.6: 24,41 SW5.3@26,41 ; 26,39 SW5.3@26,41 ; 26,43 SW5.3@26,41 ; 28,41 SW5.3@26,41 ; 30,27 CN3.2A@31.6,27 ; 30,32 CN3.2@31.6,32 ; 31.6,25.5 CN3.2A@31.6,27 ; 31.6,28.5 CN3.2A@31.6,27 ; 31.6,30.5 CN3.2@31.6,32 ; 31.6,33.5 CN3.2@31.6,32 ; 33,27 CN3.2A@31.6,27 ; 33,32 CN3.2@31.6,32 ; v1(45.2,90) TP4.1@47,90 ; v1(47,88.2) TP4.1@47,90 ; v1(47,91.8) TP4.1@47,90 ; v1(48.8,90) TP4.1@47,90
  BOTTOM w1: 52.68,92.6 CN5.4@53.9,91.38 ; 52.7,90.18 CN5.4@53.9,91.38 ; 52.78,92.8 CN5.3@53.9,93.92 ; 52.8,95.02 CN5.3@53.9,93.92 ; 54.98,95 CN5.3@53.9,93.92 ; 55,92.48 CN5.4@53.9,91.38 ; 55.02,92.8 CN5.3@53.9,93.92 ; 55.08,90.2 CN5.4@53.9,91.38
  other v1: 28.5,21 32.5,21 37.5,21 42.5,21 47.5,21 52.5,21 57.5,21 62.5,21 67.5,21 72.5,21 77.5,21 82.5,21 87.5,21 92.5,21 96.5,21 95.5,24.5 40.1,25.3 41.7,25.3 47.1,25.3 48.7,25.3 54.1,25.3 55.7,25.3 61.1,25.3 62.7,25.3 68.1,25.3 69.7,25.3 75.1,25.3 76.7,25.3 82.1,25.3 83.7,25.3 89.1,25.3 90.7,25.3 96,26 27.5,26.5 21,28.5 26,28.5 99,28.5 104,28.5 40.1,28.7 41.7,28.7 47.1,28.7 48.7,28.7 54.1,28.7 55.7,28.7 61.1,28.7 62.7,28.7 68.1,28.7 69.7,28.7 75.1,28.7 76.7,28.7 82.1,28.7 83.7,28.7 89.1,28.7 90.7,28.7 40.1,29.5 40.9,29.5 41.7,29.5 47.1,29.5 47.9,29.5 48.7,29.5 54.1,29.5 54.9,29.5 55.7,29.5 61.1,29.5 61.9,29.5 62.7,29.5 68.1,29.5 68.9,29.5 69.7,29.5 75.1,29.5 75.9,29.5 76.7,29.5 82.1,29.5 82.9,29.5 83.7,29.5 89.1,29.5 89.9,29.5 90.7,29.5 40.1,30.3 41.7,30.3 47.1,30.3 48.7,30.3 54.1,30.3 55.7,30.3 61.1,30.3 62.7,30.3 68.1,30.3 69.7,30.3 75.1,30.3 76.7,30.3 82.1,30.3 83.7,30.3 89.1,30.3 90.7,30.3 21,31 26,31 99,31 104,31 40.1,33.7 41.7,33.7 47.1,33.7 48.7,33.7 54.1,33.7 55.7,33.7 61.1,33.7 62.7,33.7 68.1,33.7 75.1,33.7 76.7,33.7 82.1,33.7 83.7,33.7 89.1,33.7 90.7,33.7 68.1,34.7 21,36 99,36 104,36 95.4,36.2 31,36.5 33.2,37.2 55,37.8 65,37.8 76,37.8 52,38 62.2,38 72.4,38 83,39 87.4,39 38,39.8 40,39.8 53.4,39.8 63.4,39.8 73.4,39.8 93,39.8 95,39.8 83.4,40.2 88,40.2 32,40.4 21,41 23,41 104,41 43.2,41.4 46.6,41.4 53.4,41.4 56.6,41.4 63.4,41.4 66.6,41.4 73.4,41.4 76.6,41.4 83.4,41.4 98.2,41.4 40,41.8 95,41.8 100.2,42 29.6,42.6 33,42.8 55.6,43 65.6,43 75.6,43 85.6,43 34.8,43.4 88,43.8 29.6,44 38,44 40,44 93,44 95,44 34.8,45.2 99.8,45.2 45,45.4 21,46 23,46 104,46 38,46.4 93,46.4 34.8,46.8 89.8,47.2 38,48 93,48 31.4,48.4 39,49.4 41,49.4 42,49.4 53.4,49.4 55.6,49.4 63.4,49.4 65.6,49.4 75.6,49.4 83.4,49.4 85.6,49.4 87.2,49.4 94,49.4 96,49.4 97,49.4 100.6,49.4 44.8,50.6 21,51 23,51 102.4,51 104,51 31,51.5 99,52.5 56,53 68,53 104,54.4 83,54.6 26,54.8 33.4,54.8 50.8,54.8 79.4,54.8 90.6,54.8 96.8,54.8 21,55 102.4,56.2 58,59 63,59 68.2,59 37.4,59.4 41.6,59.4 44.8,59.4 83.4,59.4 87.6,59.4 90.8,59.4 21,60 23,60 102.4,60 104,60 37.4,64 41.6,64 58,64 63,64 68.2,64 83.4,64 87.6,64 21,65 23,65 104,65 37.6,68.6 41.6,68.6 44.8,68.6 83.4,68.6 87.6,68.6 90.8,68.6 58,69 63,69 68.2,69 21,70 104,70 83.4,71.6 87.6,71.6 102.6,71.6 26.2,71.8 28.8,71.8 37.4,71.8 41.6,71.8 55.6,71.8 68.2,71.8 54.6,74.8 58,74.8 21,76.5 23,76.5 26,76.5 31,76.5 36,76.5 41,76.5 46,76.5 67.6,76.6 71,76.6 74,76.6 75.8,76.6 76.8,76.6 79,76.6 84,76.6 89,76.6 94,76.6 99,76.6 104,76.6 75.8,77.6 76.8,77.6 75.8,78.6 76.8,78.6 53.6,78.8 54.6,78.8 43,79.8 53.6,79.8 54.6,79.8 53.6,80.8 54.6,80.8 67.6,81 71,81 74,81 79,81 84,81 89,81 94,81 99,81 104,81 21,82 23,82 26,82 31,82 36,82 46,85.5 79,85.5 89,86 99,86 104,86 21,87 26,87 31,87 45.2,88.2 48.8,88.2 36.8,88.6 39.2,88.6 50.4,90.2 51.6,90.2 56.2,90.2 57.2,90.2 36.9,90.5 42.9,90.5 84,91 89,91 94,91 99,91 104,91 50.4,91.2 51.6,91.2 56.2,91.2 57.2,91.2 45.2,91.8 48.8,91.8 21,92 26,92 31,92 50.4,92.2 51.6,92.2 56.2,92.2 57.2,92.2 39,92.9 50.4,93.2 51.6,93.2 56.2,93.2 57.2,93.2 50.4,94.2 51.6,94.2 56.2,94.2 57.2,94.2 63,95 65.5,95 68.5,95 73.5,95 50.4,95.2 51.6,95.2 56.2,95.2 57.2,95.2 79,95.5 84,96 89,96 94,96 99,96 104,96 36.4,96.6 39.4,96.6 42.4,96.6 33.4,96.8 21,97 26,97 31,97 43,98 36.4,98.2 37,100 43,100 57.4,100.6 35.4,100.9 41.4,100.9 37,101 84,101 89,101 94,101 99,101 104,101 59.6,101.4 21,102 26,102 31,102 37,102 49.5,102 37,103 30.2,103.6 31.2,103.6 69,104 74,104 79,104 30.2,104.6 31.2,104.6 41,104.6 37,104.8 32.75,105.2 74,106 79,106 84,106 89,106 94,106 99,106 104,106 32.75,106.2 21,107 26,107 31.75,107.2 32.75,107.2 33.75,107.2 54.35,107.6 55.15,107.6 55.95,107.6 56.75,107.6 63.15,107.6 63.95,107.6 64.75,107.6 65.55,107.6 54.35,108.4 55.15,108.4 55.95,108.4 56.75,108.4 63.15,108.4 63.95,108.4 64.75,108.4 65.55,108.4 37.2,108.8 70.15,108.8 70.95,108.8 45,109 54.35,109.2 55.15,109.2 55.95,109.2 56.75,109.2 63.15,109.2 63.95,109.2 64.75,109.2 65.55,109.2 70.15,109.6 70.95,109.6 31,110.2 79,111 84,111 104,111 31,111.2 32,111.2 21,112 26,112 31,112.5 36,112.5 41,112.5 46,112.5 56.35,114.2 57.15,114.2 57.95,114.2 63.55,114.2 64.35,114.2 65.15,114.2 70.55,114.2 71.35,114.2 72.15,114.2 74,115 79,116 84,116 89,116 94,116 99,116 104,116 21,117 26,117 31,117 36,117 41,117 46,117 49.75,117 56.35,117.8 57.15,117.8 57.95,117.8 63.55,117.8 64.35,117.8 65.15,117.8 70.55,117.8 71.35,117.8 72.15,117.8 56.35,118.6 57.15,118.6 57.95,118.6 63.55,118.6 64.35,118.6 65.15,118.6 70.55,118.6 71.35,118.6 72.15,118.6 56.35,119.4 57.15,119.4 57.95,119.4 63.55,119.4 64.35,119.4 65.15,119.4 70.55,119.4 71.35,119.4 72.15,119.4 21,119.5 104,119.5 74,121 79,121 84,121 89,121 94,121 97.5,121 28,122 31,122 36,122 41,122 46,122 49.75,122 56.35,122.8 57.15,122.8 57.95,122.8 63.55,122.8 64.35,122.8 65.15,122.8 70.55,122.8 71.35,122.8 72.15,122.8 28.5,127 31,127 36,127 41,127 46,127 51,127 59,127 64,127 69,127 74,127 79,127 84,127 89,127 94,127 96.5,127
LOADA: CN2.1 CN2.1A CN2.3 CN2.3A pad.@85.25,35 pad.@86.25,35 pad.@87.25,35 pad.@88.25,35 pad.@91.4,35 pad.@92.4,35 pad.@93.4,35 pad.@94.4,35 Q7.1 Q7.2 Q7.3 | length 42.4
  TOP w0.6: 85.05,27 CN2.3A@86.4,27 ; 85.05,32 CN2.3@86.4,32 ; 86.4,25.6 CN2.3A@86.4,27 ; 86.4,28.4 CN2.3A@86.4,27 ; 86.4,30.8 CN2.3@86.4,32 ; 86.4,33.4 CN2.3@86.4,32 ; 87.85,27 CN2.3A@86.4,27 ; 87.85,32 CN2.3@86.4,32 ; 92.05,27 CN2.1A@93.4,27 ; 92.05,32 CN2.1@93.4,32 ; 93.4,25.8 CN2.1A@93.4,27 ; 93.4,28.2 CN2.1A@93.4,27 ; 93.4,30.8 CN2.1@93.4,32 ; 93.4,33.2 CN2.1@93.4,32 ; 94.65,32 CN2.1@93.4,32 ; 94.85,27 CN2.1A@93.4,27
  BOTTOM w0.6: 85.05,27 CN2.3A@86.4,27 ; 85.05,32 CN2.3@86.4,32 ; 86.4,25.6 CN2.3A@86.4,27 ; 86.4,28.4 CN2.3A@86.4,27 ; 86.4,30.8 CN2.3@86.4,32 ; 86.4,33.4 CN2.3@86.4,32 ; 87.85,27 CN2.3A@86.4,27 ; 87.85,32 CN2.3@86.4,32 ; 92.05,27 CN2.1A@93.4,27 ; 92.05,32 CN2.1@93.4,32 ; 93.4,25.8 CN2.1A@93.4,27 ; 93.4,28.2 CN2.1A@93.4,27 ; 93.4,30.8 CN2.1@93.4,32 ; 93.4,33.2 CN2.1@93.4,32 ; 94.65,32 CN2.1@93.4,32 ; 94.85,27 CN2.1A@93.4,27
LOADB: CN2.5 CN2.5A CN2.7 CN2.7A pad.@70.4,35 pad.@70.4,36 pad.@71.4,35 pad.@71.4,36 pad.@72.4,35 pad.@72.4,36 pad.@73.4,35 pad.@73.4,36 Q9.1 Q9.2 Q9.3 | length 42.4
  TOP w0.6: 71.05,27 CN2.7A@72.4,27 ; 71.05,32 CN2.7@72.4,32 ; 72.4,25.6 CN2.7A@72.4,27 ; 72.4,28.4 CN2.7A@72.4,27 ; 72.4,30.8 CN2.7@72.4,32 ; 72.4,33.4 CN2.7@72.4,32 ; 73.85,27 CN2.7A@72.4,27 ; 73.85,32 CN2.7@72.4,32 ; 78.05,27 CN2.5A@79.4,27 ; 78.05,32 CN2.5@79.4,32 ; 79.4,25.8 CN2.5A@79.4,27 ; 79.4,28.2 CN2.5A@79.4,27 ; 79.4,30.8 CN2.5@79.4,32 ; 79.4,33.2 CN2.5@79.4,32 ; 80.65,32 CN2.5@79.4,32 ; 80.85,27 CN2.5A@79.4,27
  BOTTOM w0.6: 71.05,27 CN2.7A@72.4,27 ; 71.05,32 CN2.7@72.4,32 ; 72.4,25.6 CN2.7A@72.4,27 ; 72.4,28.4 CN2.7A@72.4,27 ; 72.4,30.8 CN2.7@72.4,32 ; 72.4,33.4 CN2.7@72.4,32 ; 73.85,27 CN2.7A@72.4,27 ; 73.85,32 CN2.7@72.4,32 ; 78.05,27 CN2.5A@79.4,27 ; 78.05,32 CN2.5@79.4,32 ; 79.4,25.8 CN2.5A@79.4,27 ; 79.4,28.2 CN2.5A@79.4,27 ; 79.4,30.8 CN2.5@79.4,32 ; 79.4,33.2 CN2.5@79.4,32 ; 80.65,32 CN2.5@79.4,32 ; 80.85,27 CN2.5A@79.4,27
LOADC: CN2.9 CN2.9A CN2.11 CN2.11A pad.@57.25,35 pad.@58.25,35 pad.@59.25,35 pad.@60.25,35 pad.@63.4,35 pad.@64.4,35 pad.@65.4,35 pad.@66.4,35 Q11.1 Q11.2 Q11.3 | length 42.4
  TOP w0.6: 57.05,27 CN2.11A@58.4,27 ; 57.05,32 CN2.11@58.4,32 ; 58.4,25.6 CN2.11A@58.4,27 ; 58.4,28.4 CN2.11A@58.4,27 ; 58.4,30.8 CN2.11@58.4,32 ; 58.4,33.4 CN2.11@58.4,32 ; 59.85,27 CN2.11A@58.4,27 ; 59.85,32 CN2.11@58.4,32 ; 64.05,27 CN2.9A@65.4,27 ; 64.05,32 CN2.9@65.4,32 ; 65.4,25.8 CN2.9A@65.4,27 ; 65.4,28.2 CN2.9A@65.4,27 ; 65.4,30.8 CN2.9@65.4,32 ; 65.4,33.2 CN2.9@65.4,32 ; 66.65,32 CN2.9@65.4,32 ; 66.85,27 CN2.9A@65.4,27
  BOTTOM w0.6: 57.05,27 CN2.11A@58.4,27 ; 57.05,32 CN2.11@58.4,32 ; 58.4,25.6 CN2.11A@58.4,27 ; 58.4,28.4 CN2.11A@58.4,27 ; 58.4,30.8 CN2.11@58.4,32 ; 58.4,33.4 CN2.11@58.4,32 ; 59.85,27 CN2.11A@58.4,27 ; 59.85,32 CN2.11@58.4,32 ; 64.05,27 CN2.9A@65.4,27 ; 64.05,32 CN2.9@65.4,32 ; 65.4,25.8 CN2.9A@65.4,27 ; 65.4,28.2 CN2.9A@65.4,27 ; 65.4,30.8 CN2.9@65.4,32 ; 65.4,33.2 CN2.9@65.4,32 ; 66.65,32 CN2.9@65.4,32 ; 66.85,27 CN2.9A@65.4,27
LOADD: CN2.13 CN2.13A CN2.15 CN2.15A pad.@43.25,35 pad.@44.25,35 pad.@45.25,35 pad.@46.25,35 pad.@50.25,35 pad.@51.25,35 pad.@52.25,35 pad.@53.25,35 Q13.1 Q13.2 Q13.3 | length 42.4
  TOP w0.6: 43.05,27 CN2.15A@44.4,27 ; 43.05,32 CN2.15@44.4,32 ; 44.4,25.6 CN2.15A@44.4,27 ; 44.4,28.4 CN2.15A@44.4,27 ; 44.4,30.8 CN2.15@44.4,32 ; 44.4,33.4 CN2.15@44.4,32 ; 45.85,27 CN2.15A@44.4,27 ; 45.85,32 CN2.15@44.4,32 ; 50.05,27 CN2.13A@51.4,27 ; 50.05,32 CN2.13@51.4,32 ; 51.4,25.8 CN2.13A@51.4,27 ; 51.4,28.2 CN2.13A@51.4,27 ; 51.4,30.8 CN2.13@51.4,32 ; 51.4,33.2 CN2.13@51.4,32 ; 52.65,32 CN2.13@51.4,32 ; 52.85,27 CN2.13A@51.4,27
  BOTTOM w0.6: 43.05,27 CN2.15A@44.4,27 ; 43.05,32 CN2.15@44.4,32 ; 44.4,25.6 CN2.15A@44.4,27 ; 44.4,28.4 CN2.15A@44.4,27 ; 44.4,30.8 CN2.15@44.4,32 ; 44.4,33.4 CN2.15@44.4,32 ; 45.85,27 CN2.15A@44.4,27 ; 45.85,32 CN2.15@44.4,32 ; 50.05,27 CN2.13A@51.4,27 ; 50.05,32 CN2.13@51.4,32 ; 51.4,25.8 CN2.13A@51.4,27 ; 51.4,28.2 CN2.13A@51.4,27 ; 51.4,30.8 CN2.13@51.4,32 ; 51.4,33.2 CN2.13@51.4,32 ; 52.65,32 CN2.13@51.4,32 ; 52.85,27 CN2.13A@51.4,27
SIG15: LED1.A R5.1 | length 1.5
  TOP w0.3: R5.1@40.2,104.45 LED1.A@40.2,106
SIG46: IC2.B1 Q1.S Q2.S | length 5.5
  TOP w0.15: IC2.B1@41,97 41,96.6 41.4,96.2 42,96.2 42.6,95.6 42.6,93.2 42.425,93.025 42,93.025
SIG166: IC2.A1 pad.@39.9,92.9 pad.@42.1,90.5 Q1.G Q2.G | length 9.9
  TOP w0.15: IC2.A1@40.6,97 39.4,95.8 39.4,93.2 39.6,93 pad.@39.9,92.9 Q1.G@40.686,92.9 ; Q2.G@41.314,90.5 pad.@42.1,90.5
  TOP w0.25: Q1.G@40.686,92.9 Q1.G@40.775,92.9 ; Q2.G@41.225,90.5 Q2.G@41.314,90.5
  BOTTOM w0.15: pad.@39.9,92.9 pad.@42.1,90.5
SIG189: IC3.A1 pad.@33.9,92.9 pad.@36.1,90.5 Q3.G Q4.G | length 9.9
  TOP w0.15: IC3.A1@34.6,97 33.4,95.8 33.4,93.2 33.6,93 pad.@33.9,92.9 Q3.G@34.686,92.9 ; Q4.G@35.314,90.5 pad.@36.1,90.5
  TOP w0.25: Q3.G@34.686,92.9 Q3.G@34.775,92.9 ; Q4.G@35.225,90.5 Q4.G@35.314,90.5
  BOTTOM w0.15: pad.@33.9,92.9 pad.@36.1,90.5
SIG190: IC3.B1 Q3.S Q4.S | length 5.5
  TOP w0.15: IC3.B1@35,97 35,96.6 35.4,96.2 36,96.2 36.6,95.6 36.6,93.2 36.425,93.025 36,93.025
SIG193: C19.2 IC1.4 | length 1.3
  TOP w0.3: C19.2@30.55,105.75 IC1.4@31.8,105.75
SIG225: C7.1 IC5.6 | length 2.1
  TOP w0.3: IC5.6@97.418,45.905 C7.1@98.602,45.905
  TOP w0.6: IC5.6@96.725,45.905 IC5.6@97.418,45.905 ; C7.1@98.602,45.905 C7.1@98.8,45.905
SIG229: IC5.10 IC10.4 | length 5.3
  TOP w0.15: IC5.10@91.867,47.175 92.975,47.175 93.6,47.8 93.6,48.8 93.35,49.05 IC10.4@93.35,50.039
  TOP w0.4: IC10.4@93.35,50.039 IC10.4@93.35,50.425
  TOP w0.6: IC5.10@91.275,47.175 IC5.10@91.867,47.175
SIG230: C8.2 D2.A IC5.15 R7.2 | length 4.3
  TOP w0.3: R7.2@88.2,39.45 D2.A@89.2,39.45 ; D2.A@89.2,39.814 C8.2@89.2,40.62 ; C8.2@89.406,40.825 IC5.15@90.582,40.825
  TOP w0.4: D2.A@89.2,39.5 D2.A@89.2,39.814
  TOP w0.55: C8.2@89.2,40.825 C8.2@89.406,40.825
  TOP w0.6: IC5.15@90.582,40.825 IC5.15@91.275,40.825
  TOP w0.7: C8.2@89.2,40.62 C8.2@89.2,40.76
SIG250: C7.2 D1.A IC5.7 R6.2 | length 4.3
  TOP w0.3: IC5.7@97.418,47.175 C7.2@98.594,47.175 ; C7.2@98.8,47.416 D1.A@98.8,48.186 ; D1.A@98.8,48.55 R6.2@99.8,48.55
  TOP w0.4: D1.A@98.8,48.186 D1.A@98.8,48.5
  TOP w0.55: C7.2@98.594,47.175 C7.2@98.8,47.175
  TOP w0.6: IC5.7@96.725,47.175 IC5.7@97.418,47.175
  TOP w0.7: C7.2@98.8,47.24 C7.2@98.8,47.416
SIG275: C5.1 R4.1 R14.2 SW1.2 SW1.4 | length 18.9
  TOP w0.15: R14.2@96.746,53.6 C5.1@97.446,53.6 ; SW1.4@97.5,70 95.6,68.1 95.6,60.6 SW1.2@97.5,58.7 97.55,57.4 R4.1@97.55,54.896 ; R4.1@97.55,54.8 C5.1@97.56,53.6
  TOP w0.3: R14.2@96.65,53.6 R14.2@96.746,53.6 ; R4.1@97.55,54.8 R4.1@97.55,54.896
  TOP w0.7: C5.1@97.446,53.6 C5.1@97.56,53.6
SIG309: R2.1 SW2.L2 | length 9
  TOP w0.15: SW2.L2@73.45,62.73 75.6,60.58 75.6,56.097 75,55.497 R2.1@75,54.946
  TOP w0.3: R2.1@75,54.85 R2.1@75,54.946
